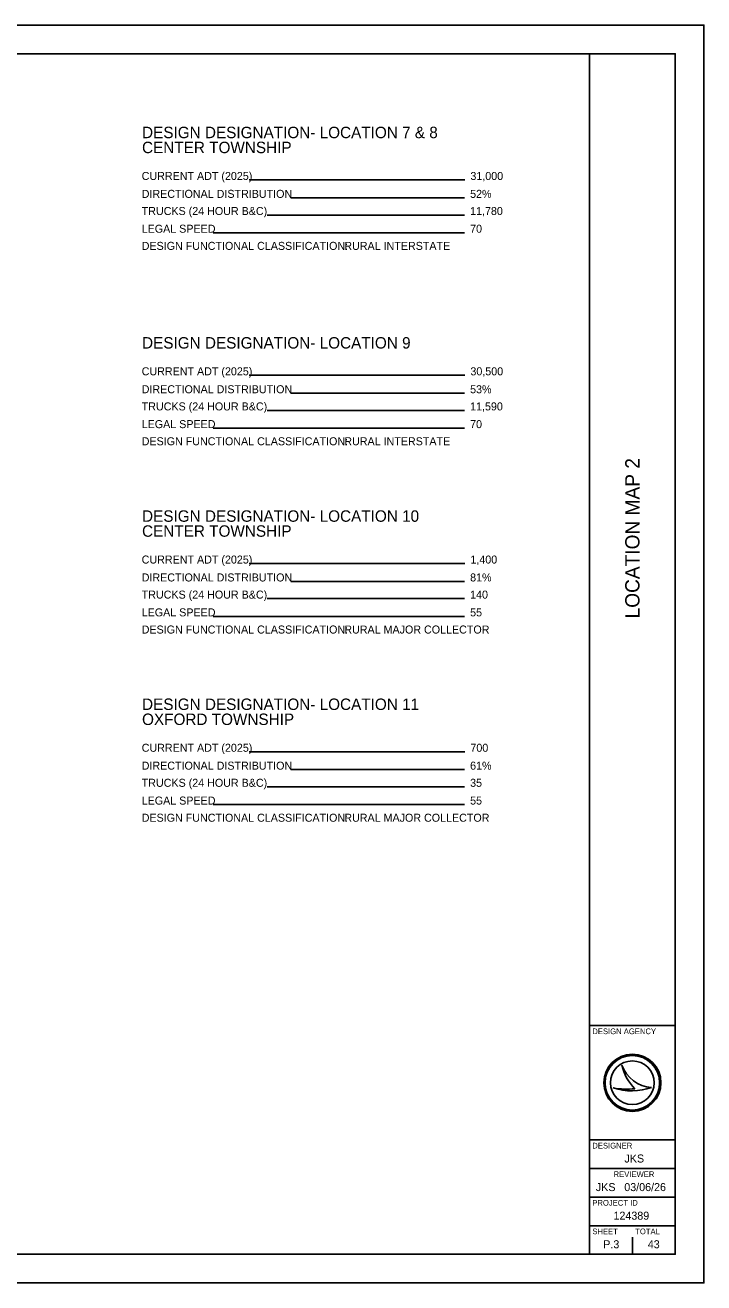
# Model space of a CAD drawing. Extents: x -29.6 to 34, y 0 to 22.
# Drawn here: x 22.13 to 34, y 0 to 22 of the extents above; entities that cross this region are included whole.
import ezdxf

# ---------------------------------------------------------------- set-up
doc = ezdxf.new("R2010")
doc.units = 0
for name, color, linetype in [('SH_Border', 7, 'Continuous'), ('SH_Cut_Line', 7, 'Continuous'), ('SH_Data', 7, 'Continuous'), ('SH_Text', 7, 'Continuous')]:
    doc.layers.add(name, color=color, linetype=linetype)

msp = doc.modelspace()

# ---------------------------------------------------------------- linework, layer by layer
at = {"layer": 'SH_Border'}
for p, q in [((32, 0.5), (32, 21.5)), ((32, 4.5), (33.5, 4.5)), ((32, 2.5), (33.5, 2.5)), ((32, 2), (33.5, 2)), ((32, 1.5), (33.5, 1.5)), ((32, 1), (33.5, 1))]:
    msp.add_line(p, q, dxfattribs=at)
msp.add_lwpolyline([(1.5, 21.5), (33.5, 21.5), (33.5, 0.5), (1.5, 0.5)], close=True, dxfattribs=at)
at = {"layer": 'SH_Cut_Line'}
msp.add_lwpolyline([(0, 0), (34, 0), (34, 22), (0, 22)], close=True, dxfattribs=at)
at = {"layer": 'SH_Data'}
for p, q in [((29.818, 19.292), (26.047, 19.292)), ((29.813, 18.979), (26.78, 18.979)), ((29.813, 18.679), (26.365, 18.679)), ((29.813, 18.369), (25.418, 18.369)), ((29.818, 15.875), (26.047, 15.875)), ((29.813, 15.561), (26.78, 15.561)), ((29.813, 15.261), (26.365, 15.261)), ((29.813, 14.951), (25.418, 14.951)), ((29.818, 12.582), (26.047, 12.582)), ((29.813, 12.269), (26.78, 12.269)), ((29.813, 11.969), (26.365, 11.969)), ((29.813, 11.658), (25.418, 11.658)), ((29.818, 9.29), (26.047, 9.29)), ((29.813, 8.977), (26.78, 8.977)), ((29.813, 8.677), (26.365, 8.677)), ((29.813, 8.366), (25.418, 8.366)), ((32.567, 3.81), (32.567, 3.81)), ((32.417, 3.41), (32.417, 3.41)), ((32.75, 3.5), (32.75, 3.5)), ((33.087, 3.419), (33.087, 3.419)), ((32.375, 0.675), (32.375, 0.675)), ((32.75, 0.5), (32.75, 0.8))]:
    msp.add_line(p, q, dxfattribs=at)
for radius in [0.5, 0.477, 0.477, 0.382]:
    msp.add_circle((32.75, 3.5), radius, dxfattribs=at)
for centre, radius, start, end in [((33.116, 3.998), 0.58, 198.9257, 198.9319), ((33.347, 3.97), 0.796, 191.6379, 191.6421), ((33.116, 3.998), 0.58, 198.9319, 267.1657), ((33.347, 3.97), 0.796, 191.6421, 226.0947), ((32.739, 4.37), 1.013, 251.4576, 290.0832), ((32.648, 4.654), 1.266, 259.4964, 259.4995), ((32.739, 4.37), 1.013, 251.4527, 251.4576), ((32.648, 4.654), 1.266, 259.4995, 276.6672)]:
    msp.add_arc(centre, radius, start, end, dxfattribs=at)

# ---------------------------------------------------------------- texts
for s, height, p in [('DESIGN DESIGNATION- LOCATION 7 & 8', 0.2, (24.176, 20.023)), ('CENTER TOWNSHIP', 0.2, (24.176, 19.761)), ('DESIGN DESIGNATION- LOCATION 9', 0.2, (24.176, 16.343)), ('DESIGN DESIGNATION- LOCATION 10', 0.2, (24.176, 13.313)), ('CENTER TOWNSHIP', 0.2, (24.176, 13.051)), ('DESIGN DESIGNATION- LOCATION 11', 0.2, (24.176, 10.021)), ('OXFORD TOWNSHIP', 0.2, (24.176, 9.758)), ('DESIGN AGENCY', 0.1, (32.05, 4.35)), ('DESIGNER', 0.1, (32.05, 2.35)), ('JKS', 0.14, (32.612, 2.105)), ('REVIEWER', 0.1, (32.422, 1.85)), ('JKS', 0.14, (32.112, 1.605)), ('03/06/26', 0.14, (32.609, 1.605)), ('PROJECT ID', 0.1, (32.05, 1.35)), ('124389', 0.14, (32.42, 1.105)), ('SHEET', 0.1, (32.05, 0.85)), ('TOTAL', 0.1, (32.8, 0.85)), ('P.3', 0.14, (32.241, 0.605)), ('43', 0.14, (33.02, 0.605))]:
    msp.add_text(s, height=height, dxfattribs=at).set_placement(p)
msp.add_text('LOCATION MAP 2', height=0.25, rotation=90, dxfattribs=at).set_placement((32.875, 11.622))
at = {"layer": 'SH_Text'}
for s, p in [('CURRENT ADT (2025)', (24.17, 19.292)), ('31,000', (29.918, 19.292)), ('DIRECTIONAL DISTRIBUTION', (24.17, 18.979)), ('52%', (29.913, 18.979)), ('TRUCKS (24 HOUR B&C)', (24.17, 18.679)), ('11,780', (29.913, 18.679)), ('LEGAL SPEED', (24.17, 18.369)), ('70', (29.913, 18.369)), ('DESIGN FUNCTIONAL CLASSIFICATION:', (24.17, 18.069)), ('RURAL INTERSTATE', (27.713, 18.069)), ('CURRENT ADT (2025)', (24.17, 15.875)), ('30,500', (29.918, 15.875)), ('DIRECTIONAL DISTRIBUTION', (24.17, 15.561)), ('53%', (29.913, 15.561)), ('TRUCKS (24 HOUR B&C)', (24.17, 15.261)), ('11,590', (29.913, 15.261)), ('LEGAL SPEED', (24.17, 14.951)), ('70', (29.913, 14.951)), ('DESIGN FUNCTIONAL CLASSIFICATION:', (24.17, 14.651)), ('RURAL INTERSTATE', (27.713, 14.651)), ('CURRENT ADT (2025)', (24.17, 12.582)), ('1,400', (29.918, 12.582)), ('DIRECTIONAL DISTRIBUTION', (24.17, 12.269)), ('81%', (29.913, 12.269)), ('TRUCKS (24 HOUR B&C)', (24.17, 11.969)), ('140', (29.913, 11.969)), ('LEGAL SPEED', (24.17, 11.658)), ('55', (29.913, 11.658)), ('DESIGN FUNCTIONAL CLASSIFICATION:', (24.17, 11.358)), ('RURAL MAJOR COLLECTOR', (27.713, 11.358)), ('CURRENT ADT (2025)', (24.17, 9.29)), ('700', (29.918, 9.29)), ('DIRECTIONAL DISTRIBUTION', (24.17, 8.977)), ('61%', (29.913, 8.977)), ('TRUCKS (24 HOUR B&C)', (24.17, 8.677)), ('35', (29.913, 8.677)), ('LEGAL SPEED', (24.17, 8.366)), ('55', (29.913, 8.366)), ('DESIGN FUNCTIONAL CLASSIFICATION:', (24.17, 8.066)), ('RURAL MAJOR COLLECTOR', (27.713, 8.066))]:
    msp.add_text(s, height=0.14, dxfattribs=at).set_placement(p)

doc.saveas('drawing.dxf')
